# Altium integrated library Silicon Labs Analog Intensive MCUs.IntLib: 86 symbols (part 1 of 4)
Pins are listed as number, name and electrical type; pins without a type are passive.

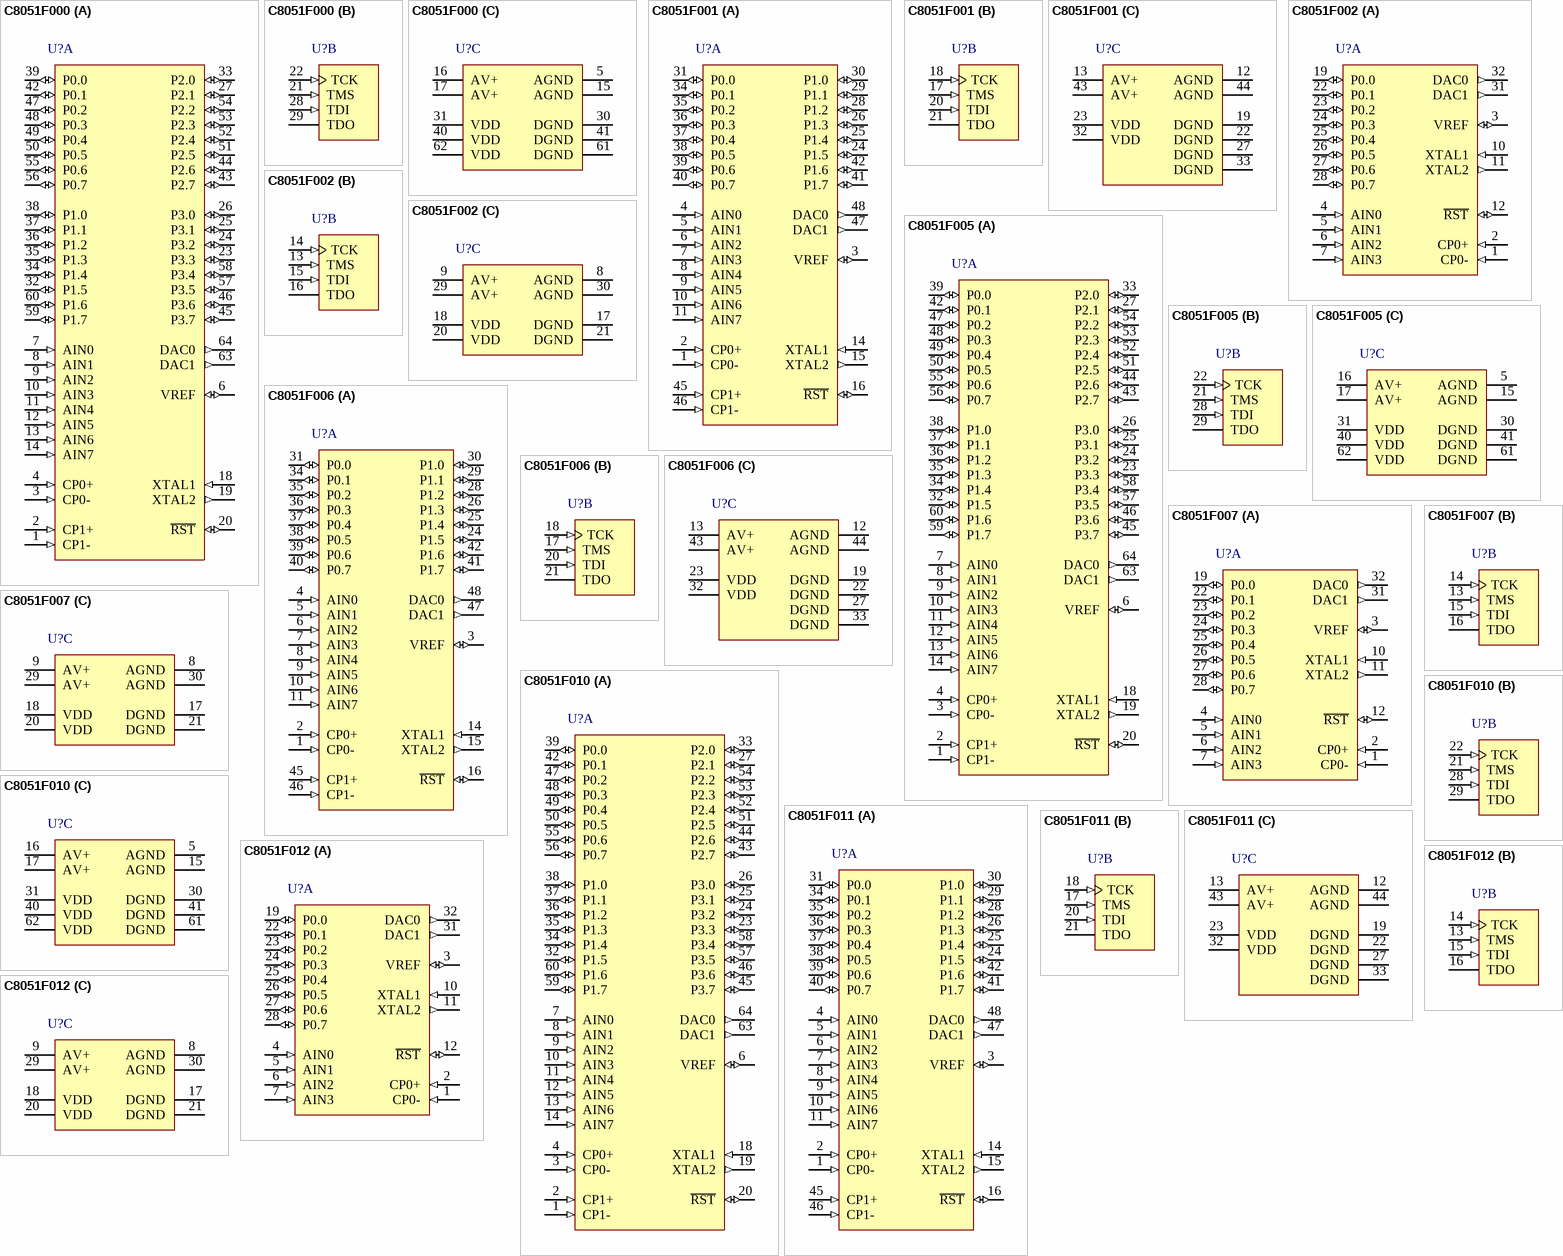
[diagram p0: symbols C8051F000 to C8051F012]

## C8051F000
designator U?
Mixed-Signal 32KB ISP FLASH MCU, 20 MIPS, 256B RAM, 32 I/Os, 12-Bit ADC, 12-Bit DAC, 64-Pin TQFP; Manufacturer: Silicon Labs; PartNumber: C8051F000
footprint TQFP-64_N (Thin QFP, 64-Leads, Body 10x10mm, Pitch 0.5mm, IPC Medium Density)
footprint TQFP-64_L (Thin QFP, 64-Leads, Body 10x10mm, Pitch 0.5mm, IPC High Density)
footprint TQFP-64_M (Thin QFP, 64-Leads, Body 10x10mm, Pitch 0.5mm, IPC Low Density)
part A pins: 1 CP1- (in), 2 CP1+ (in), 3 CP0- (in), 4 CP0+ (in), 6 VREF (io), 7 AIN0 (in), 8 AIN1 (in), 9 AIN2 (in), 10 AIN3 (in), 11 AIN4 (in), 12 AIN5 (in), 13 AIN6 (in), 14 AIN7 (in), 18 XTAL1 (in), 19 XTAL2 (out), 20 ~{RST} (io), 23 P3.3 (io), 24 P3.2 (io), 25 P3.1 (io), 26 P3.0 (io), 27 P2.1 (io), 32 P1.5 (io), 33 P2.0 (io), 34 P1.4 (io), 35 P1.3 (io), 36 P1.2 (io), 37 P1.1 (io), 38 P1.0 (io), 39 P0.0 (io), 42 P0.1 (io), 43 P2.7 (io), 44 P2.6 (io), 45 P3.7 (io), 46 P3.6 (io), 47 P0.2 (io), 48 P0.3 (io), 49 P0.4 (io), 50 P0.5 (io), 51 P2.5 (io), 52 P2.4 (io), 53 P2.3 (io), 54 P2.2 (io), 55 P0.6 (io), 56 P0.7 (io), 57 P3.5 (io), 58 P3.4 (io), 59 P1.7 (io), 60 P1.6 (io), 63 DAC1 (out), 64 DAC0 (out)
part B pins: 21 TMS (in), 22 TCK (in), 28 TDI (in), 29 TDO (hiz)
part C pins: 5 AGND (power), 15 AGND (power), 16 AV+ (power), 17 AV+ (power), 30 DGND (power), 31 VDD (power), 40 VDD (power), 41 DGND (power), 61 DGND (power), 62 VDD (power)

## C8051F001
designator U?
Mixed-Signal 32KB ISP FLASH MCU, 20 MIPS, 256B RAM, 16 I/Os, 12-Bit ADC, 12-Bit DAC, 48-Pin TQFP; Manufacturer: Silicon Labs; PartNumber: C8051F001
footprint TQFP-48_N (Thin QFP, 48-Leads, Body 7x7mm, Pitch 0.5mm, IPC Medium Density)
footprint TQFP-48_L (Thin QFP, 48-Leads, Body 7x7mm, Pitch 0.5mm, IPC High Density)
footprint TQFP-48_M (Thin QFP, 48-Leads, Body 7x7mm, Pitch 0.5mm, IPC Low Density)
part A pins: 1 CP0- (in), 2 CP0+ (in), 3 VREF (io), 4 AIN0 (in), 5 AIN1 (in), 6 AIN2 (in), 7 AIN3 (in), 8 AIN4 (in), 9 AIN5 (in), 10 AIN6 (in), 11 AIN7 (in), 14 XTAL1 (in), 15 XTAL2 (out), 16 ~{RST} (io), 24 P1.5 (io), 25 P1.4 (io), 26 P1.3 (io), 28 P1.2 (io), 29 P1.1 (io), 30 P1.0 (io), 31 P0.0 (io), 34 P0.1 (io), 35 P0.2 (io), 36 P0.3 (io), 37 P0.4 (io), 38 P0.5 (io), 39 P0.6 (io), 40 P0.7 (io), 41 P1.7 (io), 42 P1.6 (io), 45 CP1+ (in), 46 CP1- (in), 47 DAC1 (out), 48 DAC0 (out)
part B pins: 17 TMS (in), 18 TCK (in), 20 TDI (in), 21 TDO (hiz)
part C pins: 12 AGND (power), 13 AV+ (power), 19 DGND (power), 22 DGND (power), 23 VDD (power), 27 DGND (power), 32 VDD (power), 33 DGND (power), 43 AV+ (power), 44 AGND (power)

## C8051F002
designator U?
Mixed-Signal 32KB ISP FLASH MCU, 20 MIPS, 256B RAM, 8 I/Os, 12-Bit ADC, 12-Bit DAC, 32-Pin LQFP; Manufacturer: Silicon Labs; PartNumber: C8051F002
footprint LQFP-32_N (Thin QFP, 32-Leads, Body 7x7mm, Pitch 0.8mm, IPC Medium Density)
footprint LQFP-32_L (Thin QFP, 32-Leads, Body 7x7mm, Pitch 0.8mm, IPC High Density)
footprint LQFP-32_M (Thin QFP, 32-Leads, Body 7x7mm, Pitch 0.8mm, IPC Low Density)
part A pins: 1 CP0- (in), 2 CP0+ (in), 3 VREF (io), 4 AIN0 (in), 5 AIN1 (in), 6 AIN2 (in), 7 AIN3 (in), 10 XTAL1 (in), 11 XTAL2 (out), 12 ~{RST} (io), 19 P0.0 (io), 22 P0.1 (io), 23 P0.2 (io), 24 P0.3 (io), 25 P0.4 (io), 26 P0.5 (io), 27 P0.6 (io), 28 P0.7 (io), 31 DAC1 (out), 32 DAC0 (out)
part B pins: 13 TMS (in), 14 TCK (in), 15 TDI (in), 16 TDO (hiz)
part C pins: 8 AGND (power), 9 AV+ (power), 17 DGND (power), 18 VDD (power), 20 VDD (power), 21 DGND (power), 29 AV+ (power), 30 AGND (power)

## C8051F005
designator U?
Mixed-Signal 32KB ISP FLASH MCU, 25 MIPS, 2304B RAM, 32 I/Os, 12-Bit ADC, 12-Bit DAC, 64-Pin TQFP; Manufacturer: Silicon Labs; PartNumber: C8051F005
footprint TQFP-64_N (Thin QFP, 64-Leads, Body 10x10mm, Pitch 0.5mm, IPC Medium Density)
footprint TQFP-64_L (Thin QFP, 64-Leads, Body 10x10mm, Pitch 0.5mm, IPC High Density)
footprint TQFP-64_M (Thin QFP, 64-Leads, Body 10x10mm, Pitch 0.5mm, IPC Low Density)
part A pins: 1 CP1- (in), 2 CP1+ (in), 3 CP0- (in), 4 CP0+ (in), 6 VREF (io), 7 AIN0 (in), 8 AIN1 (in), 9 AIN2 (in), 10 AIN3 (in), 11 AIN4 (in), 12 AIN5 (in), 13 AIN6 (in), 14 AIN7 (in), 18 XTAL1 (in), 19 XTAL2 (out), 20 ~{RST} (io), 23 P3.3 (io), 24 P3.2 (io), 25 P3.1 (io), 26 P3.0 (io), 27 P2.1 (io), 32 P1.5 (io), 33 P2.0 (io), 34 P1.4 (io), 35 P1.3 (io), 36 P1.2 (io), 37 P1.1 (io), 38 P1.0 (io), 39 P0.0 (io), 42 P0.1 (io), 43 P2.7 (io), 44 P2.6 (io), 45 P3.7 (io), 46 P3.6 (io), 47 P0.2 (io), 48 P0.3 (io), 49 P0.4 (io), 50 P0.5 (io), 51 P2.5 (io), 52 P2.4 (io), 53 P2.3 (io), 54 P2.2 (io), 55 P0.6 (io), 56 P0.7 (io), 57 P3.5 (io), 58 P3.4 (io), 59 P1.7 (io), 60 P1.6 (io), 63 DAC1 (out), 64 DAC0 (out)
part B pins: 21 TMS (in), 22 TCK (in), 28 TDI (in), 29 TDO (hiz)
part C pins: 5 AGND (power), 15 AGND (power), 16 AV+ (power), 17 AV+ (power), 30 DGND (power), 31 VDD (power), 40 VDD (power), 41 DGND (power), 61 DGND (power), 62 VDD (power)

## C8051F006
designator U?
Mixed-Signal 32KB ISP FLASH MCU, 25 MIPS, 2304B RAM, 16 I/Os, 12-Bit ADC, 12-Bit DAC, 48-Pin TQFP; Manufacturer: Silicon Labs; PartNumber: C8051F006
footprint TQFP-48_N (Thin QFP, 48-Leads, Body 7x7mm, Pitch 0.5mm, IPC Medium Density)
footprint TQFP-48_L (Thin QFP, 48-Leads, Body 7x7mm, Pitch 0.5mm, IPC High Density)
footprint TQFP-48_M (Thin QFP, 48-Leads, Body 7x7mm, Pitch 0.5mm, IPC Low Density)
part A pins: 1 CP0- (in), 2 CP0+ (in), 3 VREF (io), 4 AIN0 (in), 5 AIN1 (in), 6 AIN2 (in), 7 AIN3 (in), 8 AIN4 (in), 9 AIN5 (in), 10 AIN6 (in), 11 AIN7 (in), 14 XTAL1 (in), 15 XTAL2 (out), 16 ~{RST} (io), 24 P1.5 (io), 25 P1.4 (io), 26 P1.3 (io), 28 P1.2 (io), 29 P1.1 (io), 30 P1.0 (io), 31 P0.0 (io), 34 P0.1 (io), 35 P0.2 (io), 36 P0.3 (io), 37 P0.4 (io), 38 P0.5 (io), 39 P0.6 (io), 40 P0.7 (io), 41 P1.7 (io), 42 P1.6 (io), 45 CP1+ (in), 46 CP1- (in), 47 DAC1 (out), 48 DAC0 (out)
part B pins: 17 TMS (in), 18 TCK (in), 20 TDI (in), 21 TDO (hiz)
part C pins: 12 AGND (power), 13 AV+ (power), 19 DGND (power), 22 DGND (power), 23 VDD (power), 27 DGND (power), 32 VDD (power), 33 DGND (power), 43 AV+ (power), 44 AGND (power)

## C8051F007
designator U?
Mixed-Signal 32KB ISP FLASH MCU, 25 MIPS, 2304B RAM, 8 I/Os, 12-Bit ADC, 12-Bit DAC, 32-Pin LQFP; Manufacturer: Silicon Labs; PartNumber: C8051F007
footprint LQFP-32_N (Thin QFP, 32-Leads, Body 7x7mm, Pitch 0.8mm, IPC Medium Density)
footprint LQFP-32_L (Thin QFP, 32-Leads, Body 7x7mm, Pitch 0.8mm, IPC High Density)
footprint LQFP-32_M (Thin QFP, 32-Leads, Body 7x7mm, Pitch 0.8mm, IPC Low Density)
part A pins: 1 CP0- (in), 2 CP0+ (in), 3 VREF (io), 4 AIN0 (in), 5 AIN1 (in), 6 AIN2 (in), 7 AIN3 (in), 10 XTAL1 (in), 11 XTAL2 (out), 12 ~{RST} (io), 19 P0.0 (io), 22 P0.1 (io), 23 P0.2 (io), 24 P0.3 (io), 25 P0.4 (io), 26 P0.5 (io), 27 P0.6 (io), 28 P0.7 (io), 31 DAC1 (out), 32 DAC0 (out)
part B pins: 13 TMS (in), 14 TCK (in), 15 TDI (in), 16 TDO (hiz)
part C pins: 8 AGND (power), 9 AV+ (power), 17 DGND (power), 18 VDD (power), 20 VDD (power), 21 DGND (power), 29 AV+ (power), 30 AGND (power)

## C8051F010
designator U?
Mixed-Signal 32KB ISP FLASH MCU, 20 MIPS, 256B RAM, 32 I/Os, 10-Bit ADC, 12-Bit DAC, 64-Pin TQFP; Manufacturer: Silicon Labs; PartNumber: C8051F010
footprint TQFP-64_N (Thin QFP, 64-Leads, Body 10x10mm, Pitch 0.5mm, IPC Medium Density)
footprint TQFP-64_L (Thin QFP, 64-Leads, Body 10x10mm, Pitch 0.5mm, IPC High Density)
footprint TQFP-64_M (Thin QFP, 64-Leads, Body 10x10mm, Pitch 0.5mm, IPC Low Density)
part A pins: 1 CP1- (in), 2 CP1+ (in), 3 CP0- (in), 4 CP0+ (in), 6 VREF (io), 7 AIN0 (in), 8 AIN1 (in), 9 AIN2 (in), 10 AIN3 (in), 11 AIN4 (in), 12 AIN5 (in), 13 AIN6 (in), 14 AIN7 (in), 18 XTAL1 (in), 19 XTAL2 (out), 20 ~{RST} (io), 23 P3.3 (io), 24 P3.2 (io), 25 P3.1 (io), 26 P3.0 (io), 27 P2.1 (io), 32 P1.5 (io), 33 P2.0 (io), 34 P1.4 (io), 35 P1.3 (io), 36 P1.2 (io), 37 P1.1 (io), 38 P1.0 (io), 39 P0.0 (io), 42 P0.1 (io), 43 P2.7 (io), 44 P2.6 (io), 45 P3.7 (io), 46 P3.6 (io), 47 P0.2 (io), 48 P0.3 (io), 49 P0.4 (io), 50 P0.5 (io), 51 P2.5 (io), 52 P2.4 (io), 53 P2.3 (io), 54 P2.2 (io), 55 P0.6 (io), 56 P0.7 (io), 57 P3.5 (io), 58 P3.4 (io), 59 P1.7 (io), 60 P1.6 (io), 63 DAC1 (out), 64 DAC0 (out)
part B pins: 21 TMS (in), 22 TCK (in), 28 TDI (in), 29 TDO (hiz)
part C pins: 5 AGND (power), 15 AGND (power), 16 AV+ (power), 17 AV+ (power), 30 DGND (power), 31 VDD (power), 40 VDD (power), 41 DGND (power), 61 DGND (power), 62 VDD (power)

## C8051F011
designator U?
Mixed-Signal 32KB ISP FLASH MCU, 20 MIPS, 256B RAM, 16 I/Os, 10-Bit ADC, 12-Bit DAC, 48-Pin TQFP; Manufacturer: Silicon Labs; PartNumber: C8051F011
footprint TQFP-48_N (Thin QFP, 48-Leads, Body 7x7mm, Pitch 0.5mm, IPC Medium Density)
footprint TQFP-48_L (Thin QFP, 48-Leads, Body 7x7mm, Pitch 0.5mm, IPC High Density)
footprint TQFP-48_M (Thin QFP, 48-Leads, Body 7x7mm, Pitch 0.5mm, IPC Low Density)
part A pins: 1 CP0- (in), 2 CP0+ (in), 3 VREF (io), 4 AIN0 (in), 5 AIN1 (in), 6 AIN2 (in), 7 AIN3 (in), 8 AIN4 (in), 9 AIN5 (in), 10 AIN6 (in), 11 AIN7 (in), 14 XTAL1 (in), 15 XTAL2 (out), 16 ~{RST} (io), 24 P1.5 (io), 25 P1.4 (io), 26 P1.3 (io), 28 P1.2 (io), 29 P1.1 (io), 30 P1.0 (io), 31 P0.0 (io), 34 P0.1 (io), 35 P0.2 (io), 36 P0.3 (io), 37 P0.4 (io), 38 P0.5 (io), 39 P0.6 (io), 40 P0.7 (io), 41 P1.7 (io), 42 P1.6 (io), 45 CP1+ (in), 46 CP1- (in), 47 DAC1 (out), 48 DAC0 (out)
part B pins: 17 TMS (in), 18 TCK (in), 20 TDI (in), 21 TDO (hiz)
part C pins: 12 AGND (power), 13 AV+ (power), 19 DGND (power), 22 DGND (power), 23 VDD (power), 27 DGND (power), 32 VDD (power), 33 DGND (power), 43 AV+ (power), 44 AGND (power)

## C8051F012
designator U?
Mixed-Signal 32KB ISP FLASH MCU, 20 MIPS, 256B RAM, 8 I/Os, 10-Bit ADC, 12-Bit DAC, 32-Pin LQFP; Manufacturer: Silicon Labs; PartNumber: C8051F012
footprint LQFP-32_N (Thin QFP, 32-Leads, Body 7x7mm, Pitch 0.8mm, IPC Medium Density)
footprint LQFP-32_L (Thin QFP, 32-Leads, Body 7x7mm, Pitch 0.8mm, IPC High Density)
footprint LQFP-32_M (Thin QFP, 32-Leads, Body 7x7mm, Pitch 0.8mm, IPC Low Density)
part A pins: 1 CP0- (in), 2 CP0+ (in), 3 VREF (io), 4 AIN0 (in), 5 AIN1 (in), 6 AIN2 (in), 7 AIN3 (in), 10 XTAL1 (in), 11 XTAL2 (out), 12 ~{RST} (io), 19 P0.0 (io), 22 P0.1 (io), 23 P0.2 (io), 24 P0.3 (io), 25 P0.4 (io), 26 P0.5 (io), 27 P0.6 (io), 28 P0.7 (io), 31 DAC1 (out), 32 DAC0 (out)
part B pins: 13 TMS (in), 14 TCK (in), 15 TDI (in), 16 TDO (hiz)
part C pins: 8 AGND (power), 9 AV+ (power), 17 DGND (power), 18 VDD (power), 20 VDD (power), 21 DGND (power), 29 AV+ (power), 30 AGND (power)

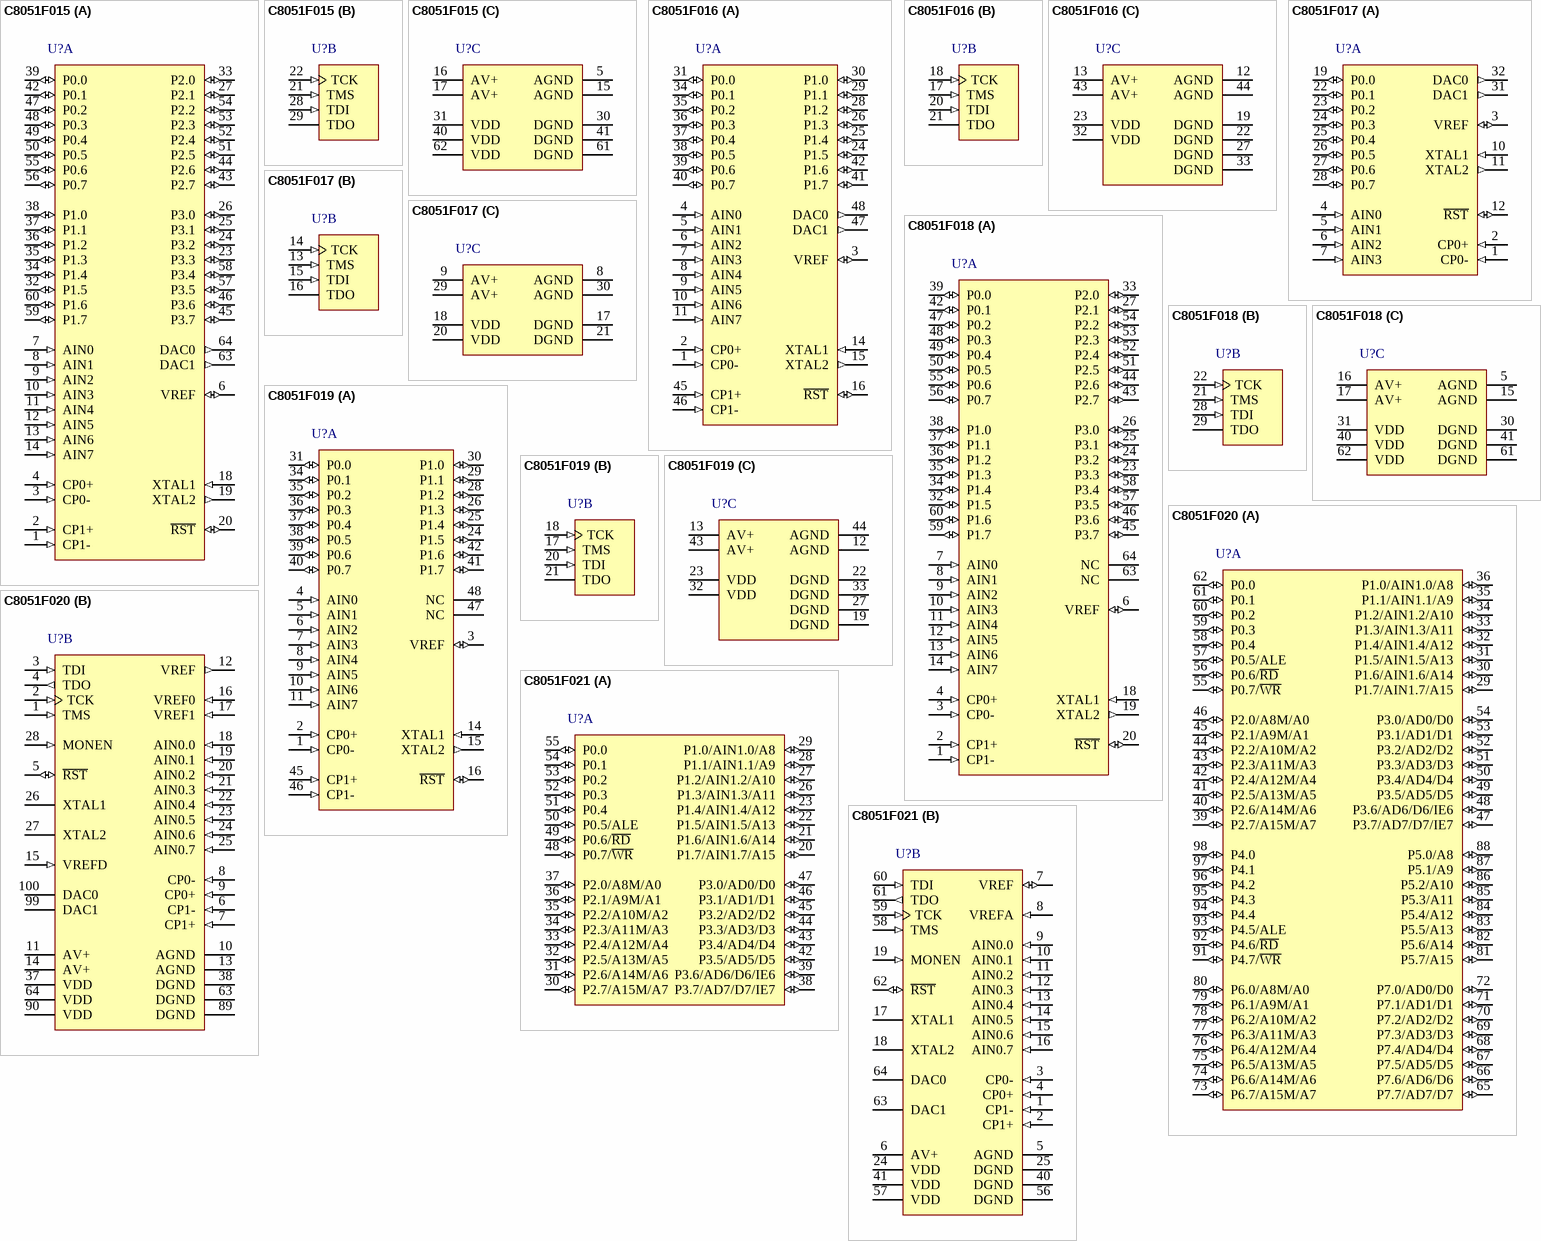
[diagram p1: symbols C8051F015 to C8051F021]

## C8051F015
designator U?
Mixed-Signal 32KB ISP FLASH MCU, 25 MIPS, 2304B RAM, 32 I/Os, 10-Bit ADC, 12-Bit DAC, 64-Pin TQFP; Manufacturer: Silicon Labs; PartNumber: C8051F015
footprint TQFP-64_N (Thin QFP, 64-Leads, Body 10x10mm, Pitch 0.5mm, IPC Medium Density)
footprint TQFP-64_L (Thin QFP, 64-Leads, Body 10x10mm, Pitch 0.5mm, IPC High Density)
footprint TQFP-64_M (Thin QFP, 64-Leads, Body 10x10mm, Pitch 0.5mm, IPC Low Density)
part A pins: 1 CP1- (in), 2 CP1+ (in), 3 CP0- (in), 4 CP0+ (in), 6 VREF (io), 7 AIN0 (in), 8 AIN1 (in), 9 AIN2 (in), 10 AIN3 (in), 11 AIN4 (in), 12 AIN5 (in), 13 AIN6 (in), 14 AIN7 (in), 18 XTAL1 (in), 19 XTAL2 (out), 20 ~{RST} (io), 23 P3.3 (io), 24 P3.2 (io), 25 P3.1 (io), 26 P3.0 (io), 27 P2.1 (io), 32 P1.5 (io), 33 P2.0 (io), 34 P1.4 (io), 35 P1.3 (io), 36 P1.2 (io), 37 P1.1 (io), 38 P1.0 (io), 39 P0.0 (io), 42 P0.1 (io), 43 P2.7 (io), 44 P2.6 (io), 45 P3.7 (io), 46 P3.6 (io), 47 P0.2 (io), 48 P0.3 (io), 49 P0.4 (io), 50 P0.5 (io), 51 P2.5 (io), 52 P2.4 (io), 53 P2.3 (io), 54 P2.2 (io), 55 P0.6 (io), 56 P0.7 (io), 57 P3.5 (io), 58 P3.4 (io), 59 P1.7 (io), 60 P1.6 (io), 63 DAC1 (out), 64 DAC0 (out)
part B pins: 21 TMS (in), 22 TCK (in), 28 TDI (in), 29 TDO (hiz)
part C pins: 5 AGND (power), 15 AGND (power), 16 AV+ (power), 17 AV+ (power), 30 DGND (power), 31 VDD (power), 40 VDD (power), 41 DGND (power), 61 DGND (power), 62 VDD (power)

## C8051F016
designator U?
Mixed-Signal 32KB ISP FLASH MCU, 25 MIPS, 2304B RAM, 16 I/Os, 10-Bit ADC, 12-Bit DAC, 48-Pin TQFP; Manufacturer: Silicon Labs; PartNumber: C8051F016
footprint TQFP-48_N (Thin QFP, 48-Leads, Body 7x7mm, Pitch 0.5mm, IPC Medium Density)
footprint TQFP-48_L (Thin QFP, 48-Leads, Body 7x7mm, Pitch 0.5mm, IPC High Density)
footprint TQFP-48_M (Thin QFP, 48-Leads, Body 7x7mm, Pitch 0.5mm, IPC Low Density)
part A pins: 1 CP0- (in), 2 CP0+ (in), 3 VREF (io), 4 AIN0 (in), 5 AIN1 (in), 6 AIN2 (in), 7 AIN3 (in), 8 AIN4 (in), 9 AIN5 (in), 10 AIN6 (in), 11 AIN7 (in), 14 XTAL1 (in), 15 XTAL2 (out), 16 ~{RST} (io), 24 P1.5 (io), 25 P1.4 (io), 26 P1.3 (io), 28 P1.2 (io), 29 P1.1 (io), 30 P1.0 (io), 31 P0.0 (io), 34 P0.1 (io), 35 P0.2 (io), 36 P0.3 (io), 37 P0.4 (io), 38 P0.5 (io), 39 P0.6 (io), 40 P0.7 (io), 41 P1.7 (io), 42 P1.6 (io), 45 CP1+ (in), 46 CP1- (in), 47 DAC1 (out), 48 DAC0 (out)
part B pins: 17 TMS (in), 18 TCK (in), 20 TDI (in), 21 TDO (hiz)
part C pins: 12 AGND (power), 13 AV+ (power), 19 DGND (power), 22 DGND (power), 23 VDD (power), 27 DGND (power), 32 VDD (power), 33 DGND (power), 43 AV+ (power), 44 AGND (power)

## C8051F017
designator U?
Mixed-Signal 32KB ISP FLASH MCU, 25 MIPS, 2304B RAM, 8 I/Os, 10-Bit ADC, 12-Bit DAC, 32-Pin LQFP; Manufacturer: Silicon Labs; PartNumber: C8051F017
footprint LQFP-32_N (Thin QFP, 32-Leads, Body 7x7mm, Pitch 0.8mm, IPC Medium Density)
footprint LQFP-32_L (Thin QFP, 32-Leads, Body 7x7mm, Pitch 0.8mm, IPC High Density)
footprint LQFP-32_M (Thin QFP, 32-Leads, Body 7x7mm, Pitch 0.8mm, IPC Low Density)
part A pins: 1 CP0- (in), 2 CP0+ (in), 3 VREF (io), 4 AIN0 (in), 5 AIN1 (in), 6 AIN2 (in), 7 AIN3 (in), 10 XTAL1 (in), 11 XTAL2 (out), 12 ~{RST} (io), 19 P0.0 (io), 22 P0.1 (io), 23 P0.2 (io), 24 P0.3 (io), 25 P0.4 (io), 26 P0.5 (io), 27 P0.6 (io), 28 P0.7 (io), 31 DAC1 (out), 32 DAC0 (out)
part B pins: 13 TMS (in), 14 TCK (in), 15 TDI (in), 16 TDO (hiz)
part C pins: 8 AGND (power), 9 AV+ (power), 17 DGND (power), 18 VDD (power), 20 VDD (power), 21 DGND (power), 29 AV+ (power), 30 AGND (power)

## C8051F018
designator U?
Mixed-Signal 16KB ISP FLASH MCU, 25 MIPS, 1280B RAM, 32 I/Os, 10-Bit ADC, 64-Pin TQFP; Manufacturer: Silicon Labs; PartNumber: C8051F018
footprint TQFP-64_N (Thin QFP, 64-Leads, Body 10x10mm, Pitch 0.5mm, IPC Medium Density)
footprint TQFP-64_L (Thin QFP, 64-Leads, Body 10x10mm, Pitch 0.5mm, IPC High Density)
footprint TQFP-64_M (Thin QFP, 64-Leads, Body 10x10mm, Pitch 0.5mm, IPC Low Density)
part A pins: 1 CP1- (in), 2 CP1+ (in), 3 CP0- (in), 4 CP0+ (in), 6 VREF (io), 7 AIN0 (in), 8 AIN1 (in), 9 AIN2 (in), 10 AIN3 (in), 11 AIN4 (in), 12 AIN5 (in), 13 AIN6 (in), 14 AIN7 (in), 18 XTAL1 (in), 19 XTAL2 (out), 20 ~{RST} (io), 23 P3.3 (io), 24 P3.2 (io), 25 P3.1 (io), 26 P3.0 (io), 27 P2.1 (io), 32 P1.5 (io), 33 P2.0 (io), 34 P1.4 (io), 35 P1.3 (io), 36 P1.2 (io), 37 P1.1 (io), 38 P1.0 (io), 39 P0.0 (io), 42 P0.1 (io), 43 P2.7 (io), 44 P2.6 (io), 45 P3.7 (io), 46 P3.6 (io), 47 P0.2 (io), 48 P0.3 (io), 49 P0.4 (io), 50 P0.5 (io), 51 P2.5 (io), 52 P2.4 (io), 53 P2.3 (io), 54 P2.2 (io), 55 P0.6 (io), 56 P0.7 (io), 57 P3.5 (io), 58 P3.4 (io), 59 P1.7 (io), 60 P1.6 (io), 63 NC, 64 NC
part B pins: 21 TMS (in), 22 TCK (in), 28 TDI (in), 29 TDO (hiz)
part C pins: 5 AGND (power), 15 AGND (power), 16 AV+ (power), 17 AV+ (power), 30 DGND (power), 31 VDD (power), 40 VDD (power), 41 DGND (power), 61 DGND (power), 62 VDD (power)

## C8051F019
designator U?
Mixed-Signal 16KB ISP FLASH MCU, 25 MIPS, 1280B RAM, 16 I/Os, 10-Bit ADC, 48-Pin TQFP; Manufacturer: Silicon Labs; PartNumber: C8051F019
footprint TQFP-48_N (Thin QFP, 48-Leads, Body 7x7mm, Pitch 0.5mm, IPC Medium Density)
footprint TQFP-48_L (Thin QFP, 48-Leads, Body 7x7mm, Pitch 0.5mm, IPC High Density)
footprint TQFP-48_M (Thin QFP, 48-Leads, Body 7x7mm, Pitch 0.5mm, IPC Low Density)
part A pins: 1 CP0- (in), 2 CP0+ (in), 3 VREF (io), 4 AIN0 (in), 5 AIN1 (in), 6 AIN2 (in), 7 AIN3 (in), 8 AIN4 (in), 9 AIN5 (in), 10 AIN6 (in), 11 AIN7 (in), 14 XTAL1 (in), 15 XTAL2 (out), 16 ~{RST} (io), 24 P1.5 (io), 25 P1.4 (io), 26 P1.3 (io), 28 P1.2 (io), 29 P1.1 (io), 30 P1.0 (io), 31 P0.0 (io), 34 P0.1 (io), 35 P0.2 (io), 36 P0.3 (io), 37 P0.4 (io), 38 P0.5 (io), 39 P0.6 (io), 40 P0.7 (io), 41 P1.7 (io), 42 P1.6 (io), 45 CP1+ (in), 46 CP1- (in), 47 NC, 48 NC
part B pins: 17 TMS (in), 18 TCK (in), 20 TDI (in), 21 TDO (hiz)
part C pins: 12 AGND (power), 13 AV+ (power), 19 DGND (power), 22 DGND (power), 23 VDD (power), 27 DGND (power), 32 VDD (power), 33 DGND (power), 43 AV+ (power), 44 AGND (power)

## C8051F020
designator U?
ISP Flash MCU Family, 25 MHz, 4.25 kB RAM, 64 kB Flash, -40 to 85 degC, 100-pin QFP; Manufacturer: Silicon Labs; PartNumber: C8051F020; ADC 1: 12-bit, 8-ch., 100 ksps; ADC 2: 8-bit, 8-ch., 500 ksps; AEC-Q100: FALSE; Comparators: 2; DAC: 12-bit, 2-ch.; Debug Interface: JTAG; Dig I/O Pins: 64; Flash: 64 kB; Internal Osc. Accuracy: +/-20%; MCU Core: 8051; MHz: 25; PCA Channels: 5; RAM: 4.25 kB; Temp Sensor: TRUE; Sub-Family: Analog Intensive MCUs
footprint SLAB-TQFP-100_N (QFP, 100-Leads, Body 14x14mm, Pitch 0.5mm, IPC Medium Density)
footprint SLAB-TQFP-100_L (QFP, 100-Leads, Body 14x14mm, Pitch 0.5mm, IPC High Density)
footprint SLAB-TQFP-100_M (QFP, 100-Leads, Body 14x14mm, Pitch 0.5mm, IPC Low Density)
part A pins: 29 P1.7/AIN1.7/A15 (io), 30 P1.6/AIN1.6/A14 (io), 31 P1.5/AIN1.5/A13 (io), 32 P1.4/AIN1.4/A12 (io), 33 P1.3/AIN1.3/A11 (io), 34 P1.2/AIN1.2/A10 (io), 35 P1.1/AIN1.1/A9 (io), 36 P1.0/AIN1.0/A8 (io), 39 P2.7/A15M/A7 (io), 40 P2.6/A14M/A6 (io), 41 P2.5/A13M/A5 (io), 42 P2.4/A12M/A4 (io), 43 P2.3/A11M/A3 (io), 44 P2.2/A10M/A2 (io), 45 P2.1/A9M/A1 (io), 46 P2.0/A8M/A0 (io), 47 P3.7/AD7/D7/IE7 (io), 48 P3.6/AD6/D6/IE6 (io), 49 P3.5/AD5/D5 (io), 50 P3.4/AD4/D4 (io), 51 P3.3/AD3/D3 (io), 52 P3.2/AD2/D2 (io), 53 P3.1/AD1/D1 (io), 54 P3.0/AD0/D0 (io), 55 P0.7/~{WR} (io), 56 P0.6/~{RD} (io), 57 P0.5/ALE (io), 58 P0.4 (io) "Port 0.4. See Port Input/Output section for complete description.", 59 P0.3 (io) "Port 0.3. See Port Input/Output section for complete description.", 60 P0.2 (io) "Port 0.2. See Port Input/Output section for complete description.", 61 P0.1 (io) "Port 0.1. See Port Input/Output section for complete description.", 62 P0.0 (io) "Port 0.0. See Port Input/Output section for complete description.", 65 P7.7/AD7/D7 (io), 66 P7.6/AD6/D6 (io), 67 P7.5/AD5/D5 (io), 68 P7.4/AD4/D4 (io), 69 P7.3/AD3/D3 (io), 70 P7.2/AD2/D2 (io), 71 P7.1/AD1/D1 (io), 72 P7.0/AD0/D0 (io), 73 P6.7/A15M/A7 (io), 74 P6.6/A14M/A6 (io), 75 P6.5/A13M/A5 (io), 76 P6.4/A12M/A4 (io), 77 P6.3/A11M/A3 (io), 78 P6.2/A10M/A2 (io), 79 P6.1/A9M/A1 (io), 80 P6.0/A8M/A0 (io), 81 P5.7/A15 (io), 82 P5.6/A14 (io), 83 P5.5/A13 (io), 84 P5.4/A12 (io), 85 P5.3/A11 (io), 86 P5.2/A10 (io), 87 P5.1/A9 (io), 88 P5.0/A8 (io), 91 P4.7/~{WR} (io), 92 P4.6/~{RD} (io), 93 P4.5/ALE (io), 94 P4.4 (io) "Port 4.4. See Port Input/Output section for complete description.", 95 P4.3 (io) "Port 4.3. See Port Input/Output section for complete description.", 96 P4.2 (io) "Port 4.2. See Port Input/Output section for complete description.", 97 P4.1 (io) "Port 4.1. See Port Input/Output section for complete description.", 98 P4.0 (io) "Port 4.0. See Port Input/Output section for complete description."
part B pins: 1 TMS (in) "JTAG Test Mode Select with internal pull-up.", 2 TCK (in) "JTAG Test Clock with internal pull-up.", 3 TDI (in) "JTAG Test Data Input with internal pull-up. TDI is latched on the rising edge of TCK.", 4 TDO (out) "JTAG Test Data Output with internal pull-up. Data is shifted out on TDO on the falling edge of TCK. TDO output is a tri-state driver.", 5 ~{RST} (io) "Device Reset. Open-drain output of internal VDD monitor. Is driven low when VDD is <2.7 V and MONEN is high. An external source can initiate a system reset by driving this pin low.", 6 CP1- (in) "Comparator 1 Inverting Input.", 7 CP1+ (in) "Comparator 1 Non-Inverting Input.", 8 CP0- (in) "Comparator 0 Inverting Input.", 9 CP0+ (in) "Comparator 0 Non-Inverting Input.", 10 AGND (power) "Analog Ground. Must be tied to Ground.", 11 AV+ (power) "Analog Supply Voltage. Must be tied to +2.7 to +3.6 V.", 12 VREF (out) "Bandgap Voltage Reference Output (all devices). DAC Voltage Reference Input (F021/3 only).", 13 AGND (power) "Analog Ground. Must be tied to Ground.", 14 AV+ (power) "Analog Supply Voltage. Must be tied to +2.7 to +3.6 V.", 15 VREFD (in) "DAC Voltage Reference Input.", 16 VREF0 (in) "ADC0 Voltage Reference Input.", 17 VREF1 (in) "ADC1 Voltage Reference Input.", 18 AIN0.0 (in) "ADC0 Input Channel 0 (See ADC0 Specification for complete description).", 19 AIN0.1 (in) "ADC0 Input Channel 1 (See ADC0 Specification for complete description).", 20 AIN0.2 (in) "ADC0 Input Channel 2 (See ADC0 Specification for complete description).", 21 AIN0.3 (in) "ADC0 Input Channel 3 (See ADC0 Specification for complete description).", 22 AIN0.4 (in) "ADC0 Input Channel 4 (See ADC0 Specification for complete description).", 23 AIN0.5 (in) "ADC0 Input Channel 5 (See ADC0 Specification for complete description).", 24 AIN0.6 (in) "ADC0 Input Channel 6 (See ADC0 Specification for complete description).", 25 AIN0.7 (in) "ADC0 Input Channel 7 (See ADC0 Specification for complete description).", 26 XTAL1 "Crystal Input. This pin is the return for the internal oscillator circuit for a crystal or ceramic resonator. For a precision internal clock, connect a crystal or ceramic resonator from XTAL1 to XTAL2. If overdriven by an (See Datasheet)", 27 XTAL2 "Crystal Output. This pin is the excitation driver for a crystal or ceramic resonator.", 28 MONEN (in) "VDD Monitor Enable. When tied high, this pin enables the internal VDD monitor, which forces a system reset when VDD is < 2.7 V. When tied low, the internal VDD monitor is disabled.", 37 VDD (power) "Digital Supply Voltage. Must be tied to +2.7 to +3.6 V.", 38 DGND (power) "Digital Ground. Must be tied to Ground.", 63 DGND (power) "Digital Ground. Must be tied to Ground.", 64 VDD (power) "Digital Supply Voltage. Must be tied to +2.7 to +3.6 V.", 89 DGND (power) "Digital Ground. Must be tied to Ground.", 90 VDD (power) "Digital Supply Voltage. Must be tied to +2.7 to +3.6 V.", 99 DAC1 (hiz) "Digital to Analog Converter 1 Voltage Output. (See DAC Specifica- tion for complete description).", 100 DAC0 (hiz) "Digital to Analog Converter 0 Voltage Output. (See DAC Specifica- tion for complete description)."

## C8051F021
designator U?
ISP Flash MCU Family, 25 MHz, 4.25 kB RAM, 64 kB Flash, -40 to 85 degC, 64-pin QFP; Manufacturer: Silicon Labs; PartNumber: C8051F021; ADC 1: 12-bit, 8-ch., 100 ksps; ADC 2: 8-bit, 8-ch., 500 ksps; AEC-Q100: FALSE; Comparators: 2; DAC: 12-bit, 2-ch.; Debug Interface: JTAG; Dig I/O Pins: 32; Flash: 64 kB; Internal Osc. Accuracy: +/-20%; MCU Core: 8051; MHz: 25; PCA Channels: 5; RAM: 4.25 kB; Temp Sensor: TRUE; Sub-Family: Analog Intensive MCUs
footprint SLAB-TQFP-64_N (QFP, 64-Leads, Body 10x10mm, Pitch 0.5mm, IPC Medium Density)
footprint SLAB-TQFP-64_L (QFP, 64-Leads, Body 10x10mm, Pitch 0.5mm, IPC High Density)
footprint SLAB-TQFP-64_M (QFP, 64-Leads, Body 10x10mm, Pitch 0.5mm, IPC Low Density)
part A pins: 20 P1.7/AIN1.7/A15 (io), 21 P1.6/AIN1.6/A14 (io), 22 P1.5/AIN1.5/A13 (io), 23 P1.4/AIN1.4/A12 (io), 26 P1.3/AIN1.3/A11 (io), 27 P1.2/AIN1.2/A10 (io), 28 P1.1/AIN1.1/A9 (io), 29 P1.0/AIN1.0/A8 (io), 30 P2.7/A15M/A7 (io), 31 P2.6/A14M/A6 (io), 32 P2.5/A13M/A5 (io), 33 P2.4/A12M/A4 (io), 34 P2.3/A11M/A3 (io), 35 P2.2/A10M/A2 (io), 36 P2.1/A9M/A1 (io), 37 P2.0/A8M/A0 (io), 38 P3.7/AD7/D7/IE7 (io), 39 P3.6/AD6/D6/IE6 (io), 42 P3.5/AD5/D5 (io), 43 P3.4/AD4/D4 (io), 44 P3.3/AD3/D3 (io), 45 P3.2/AD2/D2 (io), 46 P3.1/AD1/D1 (io), 47 P3.0/AD0/D0 (io), 48 P0.7/~{WR} (io), 49 P0.6/~{RD} (io), 50 P0.5/ALE (io), 51 P0.4 (io) "Port 0.4. See Port Input/Output section for complete description.", 52 P0.3 (io) "Port 0.3. See Port Input/Output section for complete description.", 53 P0.2 (io) "Port 0.2. See Port Input/Output section for complete description.", 54 P0.1 (io) "Port 0.1. See Port Input/Output section for complete description.", 55 P0.0 (io) "Port 0.0. See Port Input/Output section for complete description."
part B pins: 1 CP1- (in) "Comparator 1 Inverting Input.", 2 CP1+ (in) "Comparator 1 Non-Inverting Input.", 3 CP0- (in) "Comparator 0 Inverting Input.", 4 CP0+ (in) "Comparator 0 Non-Inverting Input.", 5 AGND (power) "Analog Ground. Must be tied to Ground.", 6 AV+ (power) "Analog Supply Voltage. Must be tied to +2.7 to +3.6 V.", 7 VREF (io) "Bandgap Voltage Reference Output (all devices). DAC Voltage Reference Input (F021/3 only).", 8 VREFA (in) "ADC0 and ADC1 Voltage Reference Input.", 9 AIN0.0 (in) "ADC0 Input Channel 0 (See ADC0 Specification for complete description).", 10 AIN0.1 (in) "ADC0 Input Channel 1 (See ADC0 Specification for complete description).", 11 AIN0.2 (in) "ADC0 Input Channel 2 (See ADC0 Specification for complete description).", 12 AIN0.3 (in) "ADC0 Input Channel 3 (See ADC0 Specification for complete description).", 13 AIN0.4 (in) "ADC0 Input Channel 4 (See ADC0 Specification for complete description).", 14 AIN0.5 (in) "ADC0 Input Channel 5 (See ADC0 Specification for complete description).", 15 AIN0.6 (in) "ADC0 Input Channel 6 (See ADC0 Specification for complete description).", 16 AIN0.7 (in) "ADC0 Input Channel 7 (See ADC0 Specification for complete description).", 17 XTAL1 "Crystal Input. This pin is the return for the internal oscillator circuit for a crystal or ceramic resonator. For a precision internal clock, connect a crystal or ceramic resonator from XTAL1 to XTAL2. If overdriven by an (See Datasheet)", 18 XTAL2 "Crystal Output. This pin is the excitation driver for a crystal or ceramic resonator.", 19 MONEN (in) "VDD Monitor Enable. When tied high, this pin enables the internal VDD monitor, which forces a system reset when VDD is < 2.7 V. When tied low, the internal VDD monitor is disabled.", 24 VDD (power) "Digital Supply Voltage. Must be tied to +2.7 to +3.6 V.", 25 DGND (power) "Digital Ground. Must be tied to Ground.", 40 DGND (power) "Digital Ground. Must be tied to Ground.", 41 VDD (power) "Digital Supply Voltage. Must be tied to +2.7 to +3.6 V.", 56 DGND (power) "Digital Ground. Must be tied to Ground.", 57 VDD (power) "Digital Supply Voltage. Must be tied to +2.7 to +3.6 V.", 58 TMS (in) "JTAG Test Mode Select with internal pull-up.", 59 TCK (in) "JTAG Test Clock with internal pull-up.", 60 TDI (in) "JTAG Test Data Input with internal pull-up. TDI is latched on the rising edge of TCK.", 61 TDO (out) "JTAG Test Data Output with internal pull-up. Data is shifted out on TDO on the falling edge of TCK. TDO output is a tri-state driver.", 62 ~{RST} (io) "Device Reset. Open-drain output of internal VDD monitor. Is driven low when VDD is <2.7 V and MONEN is high. An external source can initiate a system reset by driving this pin low.", 63 DAC1 (hiz) "Digital to Analog Converter 1 Voltage Output. (See DAC Specifica- tion for complete description).", 64 DAC0 (hiz) "Digital to Analog Converter 0 Voltage Output. (See DAC Specifica- tion for complete description)."

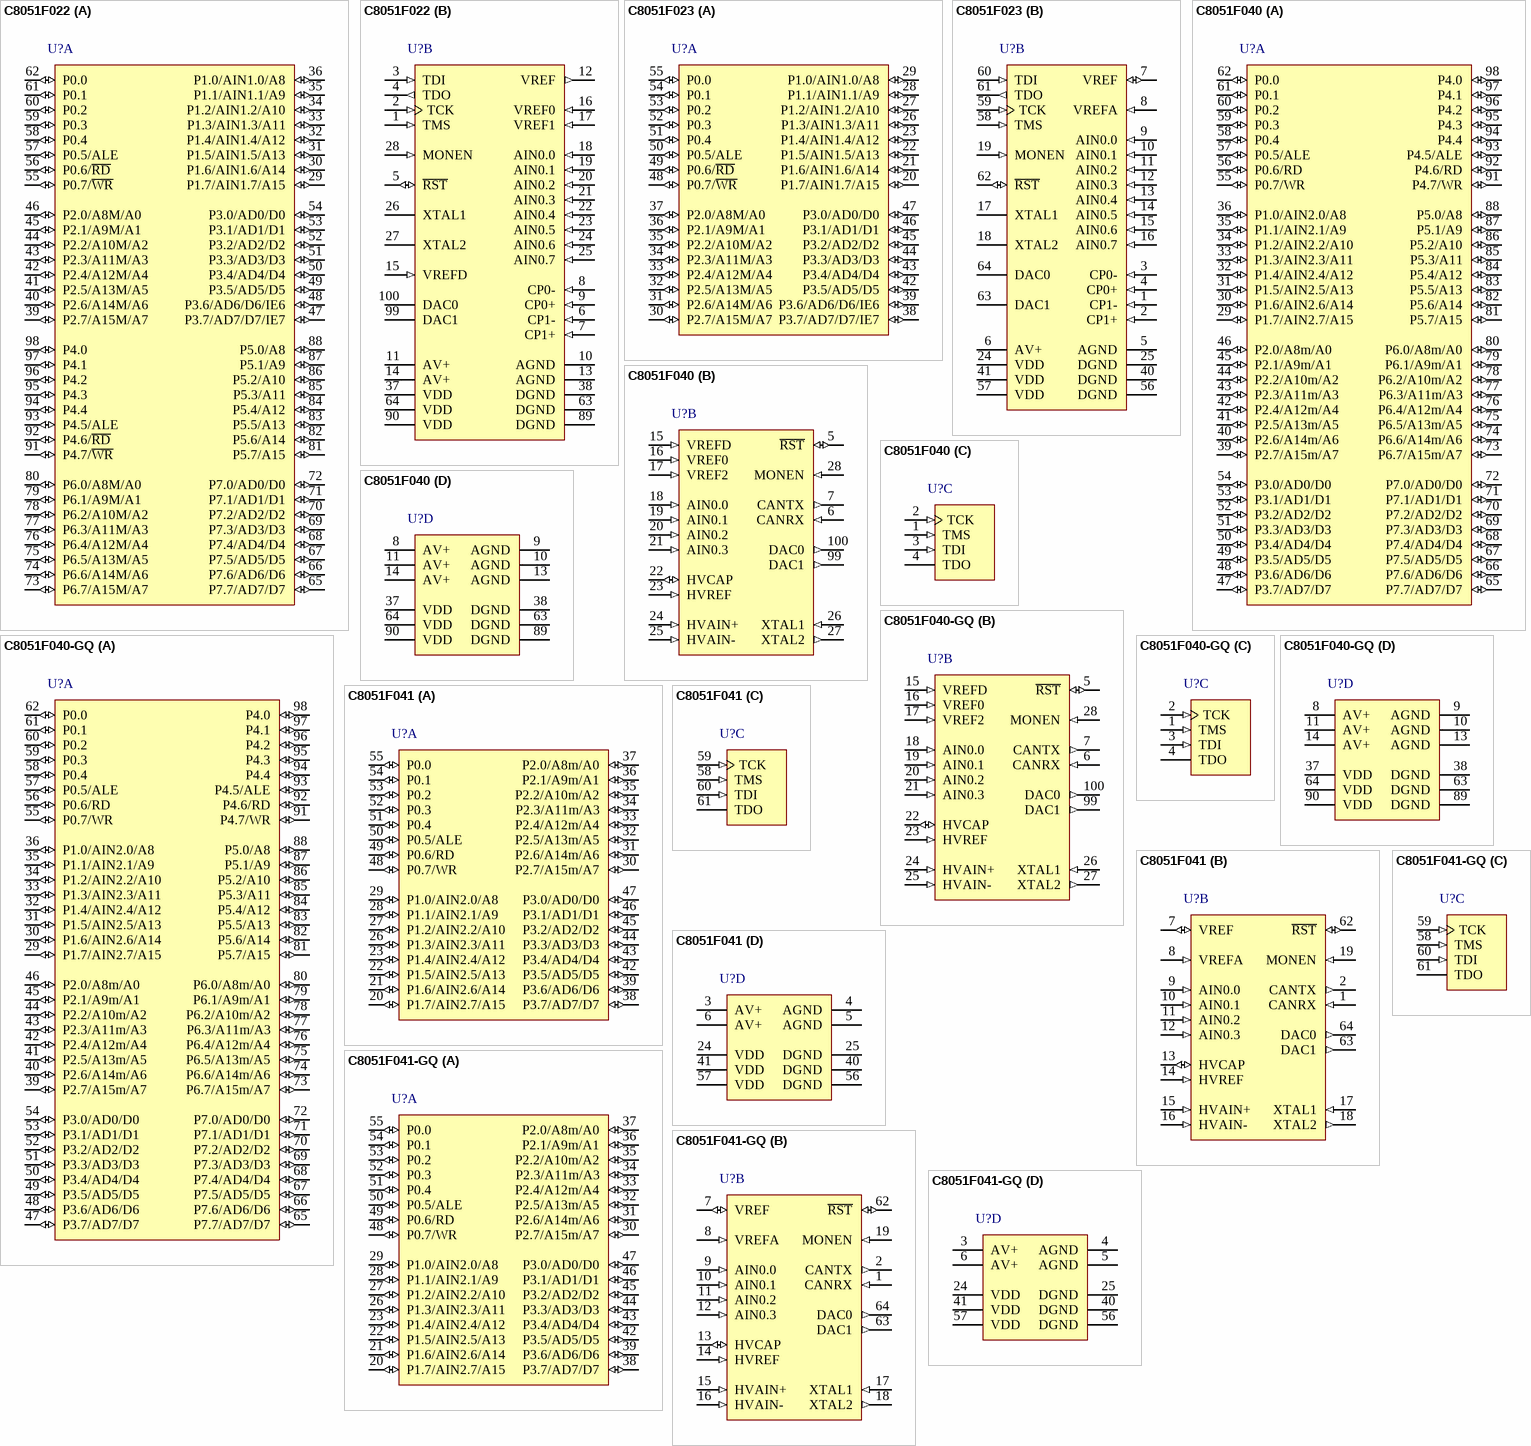
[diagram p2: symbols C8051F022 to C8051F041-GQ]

## C8051F022
designator U?
ISP Flash MCU Family, 25 MHz, 4.25 kB RAM, 64 kB Flash, -40 to 85 degC, 100-pin QFP; Manufacturer: Silicon Labs; PartNumber: C8051F022; ADC 1: 10-bit, 8-ch., 100 ksps; ADC 2: 8-bit, 8-ch., 500 ksps; AEC-Q100: FALSE; Comparators: 2; DAC: 12-bit, 2-ch.; Debug Interface: JTAG; Dig I/O Pins: 64; Flash: 64 kB; Internal Osc. Accuracy: +/-20%; MCU Core: 8051; MHz: 25; PCA Channels: 5; RAM: 4.25 kB; Temp Sensor: TRUE; Sub-Family: Analog Intensive MCUs
footprint SLAB-TQFP-100_N (QFP, 100-Leads, Body 14x14mm, Pitch 0.5mm, IPC Medium Density)
footprint SLAB-TQFP-100_L (QFP, 100-Leads, Body 14x14mm, Pitch 0.5mm, IPC High Density)
footprint SLAB-TQFP-100_M (QFP, 100-Leads, Body 14x14mm, Pitch 0.5mm, IPC Low Density)
part A pins: 29 P1.7/AIN1.7/A15 (io), 30 P1.6/AIN1.6/A14 (io), 31 P1.5/AIN1.5/A13 (io), 32 P1.4/AIN1.4/A12 (io), 33 P1.3/AIN1.3/A11 (io), 34 P1.2/AIN1.2/A10 (io), 35 P1.1/AIN1.1/A9 (io), 36 P1.0/AIN1.0/A8 (io), 39 P2.7/A15M/A7 (io), 40 P2.6/A14M/A6 (io), 41 P2.5/A13M/A5 (io), 42 P2.4/A12M/A4 (io), 43 P2.3/A11M/A3 (io), 44 P2.2/A10M/A2 (io), 45 P2.1/A9M/A1 (io), 46 P2.0/A8M/A0 (io), 47 P3.7/AD7/D7/IE7 (io), 48 P3.6/AD6/D6/IE6 (io), 49 P3.5/AD5/D5 (io), 50 P3.4/AD4/D4 (io), 51 P3.3/AD3/D3 (io), 52 P3.2/AD2/D2 (io), 53 P3.1/AD1/D1 (io), 54 P3.0/AD0/D0 (io), 55 P0.7/~{WR} (io), 56 P0.6/~{RD} (io), 57 P0.5/ALE (io), 58 P0.4 (io) "Port 0.4. See Port Input/Output section for complete description.", 59 P0.3 (io) "Port 0.3. See Port Input/Output section for complete description.", 60 P0.2 (io) "Port 0.2. See Port Input/Output section for complete description.", 61 P0.1 (io) "Port 0.1. See Port Input/Output section for complete description.", 62 P0.0 (io) "Port 0.0. See Port Input/Output section for complete description.", 65 P7.7/AD7/D7 (io), 66 P7.6/AD6/D6 (io), 67 P7.5/AD5/D5 (io), 68 P7.4/AD4/D4 (io), 69 P7.3/AD3/D3 (io), 70 P7.2/AD2/D2 (io), 71 P7.1/AD1/D1 (io), 72 P7.0/AD0/D0 (io), 73 P6.7/A15M/A7 (io), 74 P6.6/A14M/A6 (io), 75 P6.5/A13M/A5 (io), 76 P6.4/A12M/A4 (io), 77 P6.3/A11M/A3 (io), 78 P6.2/A10M/A2 (io), 79 P6.1/A9M/A1 (io), 80 P6.0/A8M/A0 (io), 81 P5.7/A15 (io), 82 P5.6/A14 (io), 83 P5.5/A13 (io), 84 P5.4/A12 (io), 85 P5.3/A11 (io), 86 P5.2/A10 (io), 87 P5.1/A9 (io), 88 P5.0/A8 (io), 91 P4.7/~{WR} (io), 92 P4.6/~{RD} (io), 93 P4.5/ALE (io), 94 P4.4 (io) "Port 4.4. See Port Input/Output section for complete description.", 95 P4.3 (io) "Port 4.3. See Port Input/Output section for complete description.", 96 P4.2 (io) "Port 4.2. See Port Input/Output section for complete description.", 97 P4.1 (io) "Port 4.1. See Port Input/Output section for complete description.", 98 P4.0 (io) "Port 4.0. See Port Input/Output section for complete description."
part B pins: 1 TMS (in) "JTAG Test Mode Select with internal pull-up.", 2 TCK (in) "JTAG Test Clock with internal pull-up.", 3 TDI (in) "JTAG Test Data Input with internal pull-up. TDI is latched on the rising edge of TCK.", 4 TDO (out) "JTAG Test Data Output with internal pull-up. Data is shifted out on TDO on the falling edge of TCK. TDO output is a tri-state driver.", 5 ~{RST} (io) "Device Reset. Open-drain output of internal VDD monitor. Is driven low when VDD is <2.7 V and MONEN is high. An external source can initiate a system reset by driving this pin low.", 6 CP1- (in) "Comparator 1 Inverting Input.", 7 CP1+ (in) "Comparator 1 Non-Inverting Input.", 8 CP0- (in) "Comparator 0 Inverting Input.", 9 CP0+ (in) "Comparator 0 Non-Inverting Input.", 10 AGND (power) "Analog Ground. Must be tied to Ground.", 11 AV+ (power) "Analog Supply Voltage. Must be tied to +2.7 to +3.6 V.", 12 VREF (out) "Bandgap Voltage Reference Output (all devices). DAC Voltage Reference Input (F021/3 only).", 13 AGND (power) "Analog Ground. Must be tied to Ground.", 14 AV+ (power) "Analog Supply Voltage. Must be tied to +2.7 to +3.6 V.", 15 VREFD (in) "DAC Voltage Reference Input.", 16 VREF0 (in) "ADC0 Voltage Reference Input.", 17 VREF1 (in) "ADC1 Voltage Reference Input.", 18 AIN0.0 (in) "ADC0 Input Channel 0 (See ADC0 Specification for complete description).", 19 AIN0.1 (in) "ADC0 Input Channel 1 (See ADC0 Specification for complete description).", 20 AIN0.2 (in) "ADC0 Input Channel 2 (See ADC0 Specification for complete description).", 21 AIN0.3 (in) "ADC0 Input Channel 3 (See ADC0 Specification for complete description).", 22 AIN0.4 (in) "ADC0 Input Channel 4 (See ADC0 Specification for complete description).", 23 AIN0.5 (in) "ADC0 Input Channel 5 (See ADC0 Specification for complete description).", 24 AIN0.6 (in) "ADC0 Input Channel 6 (See ADC0 Specification for complete description).", 25 AIN0.7 (in) "ADC0 Input Channel 7 (See ADC0 Specification for complete description).", 26 XTAL1 "Crystal Input. This pin is the return for the internal oscillator circuit for a crystal or ceramic resonator. For a precision internal clock, connect a crystal or ceramic resonator from XTAL1 to XTAL2. If overdriven by an (See Datasheet)", 27 XTAL2 "Crystal Output. This pin is the excitation driver for a crystal or ceramic resonator.", 28 MONEN (in) "VDD Monitor Enable. When tied high, this pin enables the internal VDD monitor, which forces a system reset when VDD is < 2.7 V. When tied low, the internal VDD monitor is disabled.", 37 VDD (power) "Digital Supply Voltage. Must be tied to +2.7 to +3.6 V.", 38 DGND (power) "Digital Ground. Must be tied to Ground.", 63 DGND (power) "Digital Ground. Must be tied to Ground.", 64 VDD (power) "Digital Supply Voltage. Must be tied to +2.7 to +3.6 V.", 89 DGND (power) "Digital Ground. Must be tied to Ground.", 90 VDD (power) "Digital Supply Voltage. Must be tied to +2.7 to +3.6 V.", 99 DAC1 (hiz) "Digital to Analog Converter 1 Voltage Output. (See DAC Specifica- tion for complete description).", 100 DAC0 (hiz) "Digital to Analog Converter 0 Voltage Output. (See DAC Specifica- tion for complete description)."

## C8051F023
designator U?
ISP Flash MCU Family, 25 MHz, 4.25 kB RAM, 64 kB Flash, -40 to 85 degC, 64-pin QFP; Manufacturer: Silicon Labs; PartNumber: C8051F023; ADC 1: 10-bit, 8-ch., 100 ksps; ADC 2: 8-bit, 8-ch., 500 ksps; AEC-Q100: FALSE; Comparators: 2; DAC: 12-bit, 2-ch.; Debug Interface: JTAG; Dig I/O Pins: 32; Flash: 64 kB; Internal Osc. Accuracy: +/-20%; MCU Core: 8051; MHz: 25; PCA Channels: 5; RAM: 4.25 kB; Temp Sensor: TRUE; Sub-Family: Analog Intensive MCUs
footprint SLAB-TQFP-64_N (QFP, 64-Leads, Body 10x10mm, Pitch 0.5mm, IPC Medium Density)
footprint SLAB-TQFP-64_L (QFP, 64-Leads, Body 10x10mm, Pitch 0.5mm, IPC High Density)
footprint SLAB-TQFP-64_M (QFP, 64-Leads, Body 10x10mm, Pitch 0.5mm, IPC Low Density)
part A pins: 20 P1.7/AIN1.7/A15 (io), 21 P1.6/AIN1.6/A14 (io), 22 P1.5/AIN1.5/A13 (io), 23 P1.4/AIN1.4/A12 (io), 26 P1.3/AIN1.3/A11 (io), 27 P1.2/AIN1.2/A10 (io), 28 P1.1/AIN1.1/A9 (io), 29 P1.0/AIN1.0/A8 (io), 30 P2.7/A15M/A7 (io), 31 P2.6/A14M/A6 (io), 32 P2.5/A13M/A5 (io), 33 P2.4/A12M/A4 (io), 34 P2.3/A11M/A3 (io), 35 P2.2/A10M/A2 (io), 36 P2.1/A9M/A1 (io), 37 P2.0/A8M/A0 (io), 38 P3.7/AD7/D7/IE7 (io), 39 P3.6/AD6/D6/IE6 (io), 42 P3.5/AD5/D5 (io), 43 P3.4/AD4/D4 (io), 44 P3.3/AD3/D3 (io), 45 P3.2/AD2/D2 (io), 46 P3.1/AD1/D1 (io), 47 P3.0/AD0/D0 (io), 48 P0.7/~{WR} (io), 49 P0.6/~{RD} (io), 50 P0.5/ALE (io), 51 P0.4 (io) "Port 0.4. See Port Input/Output section for complete description.", 52 P0.3 (io) "Port 0.3. See Port Input/Output section for complete description.", 53 P0.2 (io) "Port 0.2. See Port Input/Output section for complete description.", 54 P0.1 (io) "Port 0.1. See Port Input/Output section for complete description.", 55 P0.0 (io) "Port 0.0. See Port Input/Output section for complete description."
part B pins: 1 CP1- (in) "Comparator 1 Inverting Input.", 2 CP1+ (in) "Comparator 1 Non-Inverting Input.", 3 CP0- (in) "Comparator 0 Inverting Input.", 4 CP0+ (in) "Comparator 0 Non-Inverting Input.", 5 AGND (power) "Analog Ground. Must be tied to Ground.", 6 AV+ (power) "Analog Supply Voltage. Must be tied to +2.7 to +3.6 V.", 7 VREF (io) "Bandgap Voltage Reference Output (all devices). DAC Voltage Reference Input (F021/3 only).", 8 VREFA (in) "ADC0 and ADC1 Voltage Reference Input.", 9 AIN0.0 (in) "ADC0 Input Channel 0 (See ADC0 Specification for complete description).", 10 AIN0.1 (in) "ADC0 Input Channel 1 (See ADC0 Specification for complete description).", 11 AIN0.2 (in) "ADC0 Input Channel 2 (See ADC0 Specification for complete description).", 12 AIN0.3 (in) "ADC0 Input Channel 3 (See ADC0 Specification for complete description).", 13 AIN0.4 (in) "ADC0 Input Channel 4 (See ADC0 Specification for complete description).", 14 AIN0.5 (in) "ADC0 Input Channel 5 (See ADC0 Specification for complete description).", 15 AIN0.6 (in) "ADC0 Input Channel 6 (See ADC0 Specification for complete description).", 16 AIN0.7 (in) "ADC0 Input Channel 7 (See ADC0 Specification for complete description).", 17 XTAL1 "Crystal Input. This pin is the return for the internal oscillator circuit for a crystal or ceramic resonator. For a precision internal clock, connect a crystal or ceramic resonator from XTAL1 to XTAL2. If overdriven by an (See Datasheet)", 18 XTAL2 "Crystal Output. This pin is the excitation driver for a crystal or ceramic resonator.", 19 MONEN (in) "VDD Monitor Enable. When tied high, this pin enables the internal VDD monitor, which forces a system reset when VDD is < 2.7 V. When tied low, the internal VDD monitor is disabled.", 24 VDD (power) "Digital Supply Voltage. Must be tied to +2.7 to +3.6 V.", 25 DGND (power) "Digital Ground. Must be tied to Ground.", 40 DGND (power) "Digital Ground. Must be tied to Ground.", 41 VDD (power) "Digital Supply Voltage. Must be tied to +2.7 to +3.6 V.", 56 DGND (power) "Digital Ground. Must be tied to Ground.", 57 VDD (power) "Digital Supply Voltage. Must be tied to +2.7 to +3.6 V.", 58 TMS (in) "JTAG Test Mode Select with internal pull-up.", 59 TCK (in) "JTAG Test Clock with internal pull-up.", 60 TDI (in) "JTAG Test Data Input with internal pull-up. TDI is latched on the rising edge of TCK.", 61 TDO (out) "JTAG Test Data Output with internal pull-up. Data is shifted out on TDO on the falling edge of TCK. TDO output is a tri-state driver.", 62 ~{RST} (io) "Device Reset. Open-drain output of internal VDD monitor. Is driven low when VDD is <2.7 V and MONEN is high. An external source can initiate a system reset by driving this pin low.", 63 DAC1 (hiz) "Digital to Analog Converter 1 Voltage Output. (See DAC Specifica- tion for complete description).", 64 DAC0 (hiz) "Digital to Analog Converter 0 Voltage Output. (See DAC Specifica- tion for complete description)."

## C8051F040
designator U?
Mixed Signal 64KB ISP Flash MCU, 25 MIPS, 4352B RAM, 64 I/Os, 12-Bit & 8-Bit ADC, 12-Bit DAC, 100-Pin TQFP; Manufacturer: Silicon Labs; PartNumber: C8051F040
footprint TQFP-100_N (Thin QFP, 100-Leads, Body 14x14mm, Pitch 0.5mm, IPC Medium Density)
footprint TQFP-100_L (Thin QFP, 100-Leads, Body 14x14mm, Pitch 0.5mm, IPC High Density)
footprint TQFP-100_M (Thin QFP, 100-Leads, Body 14x14mm, Pitch 0.5mm, IPC Low Density)
part A pins: 29 P1.7/AIN2.7/A15 (io), 30 P1.6/AIN2.6/A14 (io), 31 P1.5/AIN2.5/A13 (io), 32 P1.4/AIN2.4/A12 (io), 33 P1.3/AIN2.3/A11 (io), 34 P1.2/AIN2.2/A10 (io), 35 P1.1/AIN2.1/A9 (io), 36 P1.0/AIN2.0/A8 (io), 39 P2.7/A15m/A7 (io), 40 P2.6/A14m/A6 (io), 41 P2.5/A13m/A5 (io), 42 P2.4/A12m/A4 (io), 43 P2.3/A11m/A3 (io), 44 P2.2/A10m/A2 (io), 45 P2.1/A9m/A1 (io), 46 P2.0/A8m/A0 (io), 47 P3.7/AD7/D7 (io), 48 P3.6/AD6/D6 (io), 49 P3.5/AD5/D5 (io), 50 P3.4/AD4/D4 (io), 51 P3.3/AD3/D3 (io), 52 P3.2/AD2/D2 (io), 53 P3.1/AD1/D1 (io), 54 P3.0/AD0/D0 (io), 55 P0.7/WR (io), 56 P0.6/RD (io), 57 P0.5/ALE (io), 58 P0.4 (io), 59 P0.3 (io), 60 P0.2 (io), 61 P0.1 (io), 62 P0.0 (io), 65 P7.7/AD7/D7 (io), 66 P7.6/AD6/D6 (io), 67 P7.5/AD5/D5 (io), 68 P7.4/AD4/D4 (io), 69 P7.3/AD3/D3 (io), 70 P7.2/AD2/D2 (io), 71 P7.1/AD1/D1 (io), 72 P7.0/AD0/D0 (io), 73 P6.7/A15m/A7 (io), 74 P6.6/A14m/A6 (io), 75 P6.5/A13m/A5 (io), 76 P6.4/A12m/A4 (io), 77 P6.3/A11m/A3 (io), 78 P6.2/A10m/A2 (io), 79 P6.1/A9m/A1 (io), 80 P6.0/A8m/A0 (io), 81 P5.7/A15 (io), 82 P5.6/A14 (io), 83 P5.5/A13 (io), 84 P5.4/A12 (io), 85 P5.3/A11 (io), 86 P5.2/A10 (io), 87 P5.1/A9 (io), 88 P5.0/A8 (io), 91 P4.7/WR (io), 92 P4.6/RD (io), 93 P4.5/ALE (io), 94 P4.4 (io), 95 P4.3 (io), 96 P4.2 (io), 97 P4.1 (io), 98 P4.0 (io)
part B pins: 5 ~{RST} (io), 6 CANRX (in), 7 CANTX (out), 15 VREFD (in), 16 VREF0 (in), 17 VREF2 (in), 18 AIN0.0 (in), 19 AIN0.1 (in), 20 AIN0.2 (in), 21 AIN0.3 (in), 22 HVCAP (io), 23 HVREF (in), 24 HVAIN+ (in), 25 HVAIN- (in), 26 XTAL1 (in), 27 XTAL2 (out), 28 MONEN (in), 99 DAC1 (out), 100 DAC0 (out)
part C pins: 1 TMS (in), 2 TCK (in), 3 TDI (in), 4 TDO (hiz)
part D pins: 8 AV+ (power), 9 AGND (power), 10 AGND (power), 11 AV+ (power), 13 AGND (power), 14 AV+ (power), 37 VDD (power), 38 DGND (power), 63 DGND (power), 64 VDD (power), 89 DGND (power), 90 VDD (power)

## C8051F040-GQ
designator U?
Mixed Signal 64KB ISP Flash MCU, 25 MIPS, 4352B RAM, 64 I/Os, 12-Bit & 8-Bit ADC, 12-Bit DAC, 100-Pin TQFP, Pb-Free; Manufacturer: Silicon Labs; PartNumber: C8051F040-GQ
footprint TQFP-100_N (Thin QFP, 100-Leads, Body 14x14mm, Pitch 0.5mm, IPC Medium Density)
footprint TQFP-100_L (Thin QFP, 100-Leads, Body 14x14mm, Pitch 0.5mm, IPC High Density)
footprint TQFP-100_M (Thin QFP, 100-Leads, Body 14x14mm, Pitch 0.5mm, IPC Low Density)
part A pins: 29 P1.7/AIN2.7/A15 (io), 30 P1.6/AIN2.6/A14 (io), 31 P1.5/AIN2.5/A13 (io), 32 P1.4/AIN2.4/A12 (io), 33 P1.3/AIN2.3/A11 (io), 34 P1.2/AIN2.2/A10 (io), 35 P1.1/AIN2.1/A9 (io), 36 P1.0/AIN2.0/A8 (io), 39 P2.7/A15m/A7 (io), 40 P2.6/A14m/A6 (io), 41 P2.5/A13m/A5 (io), 42 P2.4/A12m/A4 (io), 43 P2.3/A11m/A3 (io), 44 P2.2/A10m/A2 (io), 45 P2.1/A9m/A1 (io), 46 P2.0/A8m/A0 (io), 47 P3.7/AD7/D7 (io), 48 P3.6/AD6/D6 (io), 49 P3.5/AD5/D5 (io), 50 P3.4/AD4/D4 (io), 51 P3.3/AD3/D3 (io), 52 P3.2/AD2/D2 (io), 53 P3.1/AD1/D1 (io), 54 P3.0/AD0/D0 (io), 55 P0.7/WR (io), 56 P0.6/RD (io), 57 P0.5/ALE (io), 58 P0.4 (io), 59 P0.3 (io), 60 P0.2 (io), 61 P0.1 (io), 62 P0.0 (io), 65 P7.7/AD7/D7 (io), 66 P7.6/AD6/D6 (io), 67 P7.5/AD5/D5 (io), 68 P7.4/AD4/D4 (io), 69 P7.3/AD3/D3 (io), 70 P7.2/AD2/D2 (io), 71 P7.1/AD1/D1 (io), 72 P7.0/AD0/D0 (io), 73 P6.7/A15m/A7 (io), 74 P6.6/A14m/A6 (io), 75 P6.5/A13m/A5 (io), 76 P6.4/A12m/A4 (io), 77 P6.3/A11m/A3 (io), 78 P6.2/A10m/A2 (io), 79 P6.1/A9m/A1 (io), 80 P6.0/A8m/A0 (io), 81 P5.7/A15 (io), 82 P5.6/A14 (io), 83 P5.5/A13 (io), 84 P5.4/A12 (io), 85 P5.3/A11 (io), 86 P5.2/A10 (io), 87 P5.1/A9 (io), 88 P5.0/A8 (io), 91 P4.7/WR (io), 92 P4.6/RD (io), 93 P4.5/ALE (io), 94 P4.4 (io), 95 P4.3 (io), 96 P4.2 (io), 97 P4.1 (io), 98 P4.0 (io)
part B pins: 5 ~{RST} (io), 6 CANRX (in), 7 CANTX (out), 15 VREFD (in), 16 VREF0 (in), 17 VREF2 (in), 18 AIN0.0 (in), 19 AIN0.1 (in), 20 AIN0.2 (in), 21 AIN0.3 (in), 22 HVCAP (io), 23 HVREF (in), 24 HVAIN+ (in), 25 HVAIN- (in), 26 XTAL1 (in), 27 XTAL2 (out), 28 MONEN (in), 99 DAC1 (out), 100 DAC0 (out)
part C pins: 1 TMS (in), 2 TCK (in), 3 TDI (in), 4 TDO (hiz)
part D pins: 8 AV+ (power), 9 AGND (power), 10 AGND (power), 11 AV+ (power), 13 AGND (power), 14 AV+ (power), 37 VDD (power), 38 DGND (power), 63 DGND (power), 64 VDD (power), 89 DGND (power), 90 VDD (power)

## C8051F041
designator U?
Mixed Signal 64KB ISP Flash MCU, 25 MIPS, 4352B RAM, 32 I/Os, 12-Bit & 8-Bit ADC, 12-Bit DAC, 64-Pin TQFP; Manufacturer: Silicon Labs; PartNumber: C8051F041
footprint TQFP-64_N (Thin QFP, 64-Leads, Body 10x10mm, Pitch 0.5mm, IPC Medium Density)
footprint TQFP-64_L (Thin QFP, 64-Leads, Body 10x10mm, Pitch 0.5mm, IPC High Density)
footprint TQFP-64_M (Thin QFP, 64-Leads, Body 10x10mm, Pitch 0.5mm, IPC Low Density)
part A pins: 20 P1.7/AIN2.7/A15 (io), 21 P1.6/AIN2.6/A14 (io), 22 P1.5/AIN2.5/A13 (io), 23 P1.4/AIN2.4/A12 (io), 26 P1.3/AIN2.3/A11 (io), 27 P1.2/AIN2.2/A10 (io), 28 P1.1/AIN2.1/A9 (io), 29 P1.0/AIN2.0/A8 (io), 30 P2.7/A15m/A7 (io), 31 P2.6/A14m/A6 (io), 32 P2.5/A13m/A5 (io), 33 P2.4/A12m/A4 (io), 34 P2.3/A11m/A3 (io), 35 P2.2/A10m/A2 (io), 36 P2.1/A9m/A1 (io), 37 P2.0/A8m/A0 (io), 38 P3.7/AD7/D7 (io), 39 P3.6/AD6/D6 (io), 42 P3.5/AD5/D5 (io), 43 P3.4/AD4/D4 (io), 44 P3.3/AD3/D3 (io), 45 P3.2/AD2/D2 (io), 46 P3.1/AD1/D1 (io), 47 P3.0/AD0/D0 (io), 48 P0.7/WR (io), 49 P0.6/RD (io), 50 P0.5/ALE (io), 51 P0.4 (io), 52 P0.3 (io), 53 P0.2 (io), 54 P0.1 (io), 55 P0.0 (io)
part B pins: 1 CANRX (in), 2 CANTX (out), 7 VREF (io), 8 VREFA (in), 9 AIN0.0 (in), 10 AIN0.1 (in), 11 AIN0.2 (in), 12 AIN0.3 (in), 13 HVCAP (io), 14 HVREF (in), 15 HVAIN+ (in), 16 HVAIN- (in), 17 XTAL1 (in), 18 XTAL2 (out), 19 MONEN (in), 62 ~{RST} (io), 63 DAC1 (out), 64 DAC0 (out)
part C pins: 58 TMS (in), 59 TCK (in), 60 TDI (in), 61 TDO (hiz)
part D pins: 3 AV+ (power), 4 AGND (power), 5 AGND (power), 6 AV+ (power), 24 VDD (power), 25 DGND (power), 40 DGND (power), 41 VDD (power), 56 DGND (power), 57 VDD (power)

## C8051F041-GQ
designator U?
Mixed Signal 64KB ISP Flash MCU, 25 MIPS, 4352B RAM, 32 I/Os, 12-Bit & 8-Bit ADC, 12-Bit DAC, 64-Pin TQFP, Pb-Free; Manufacturer: Silicon Labs; PartNumber: C8051F041-GQ
footprint TQFP-64_N (Thin QFP, 64-Leads, Body 10x10mm, Pitch 0.5mm, IPC Medium Density)
footprint TQFP-64_L (Thin QFP, 64-Leads, Body 10x10mm, Pitch 0.5mm, IPC High Density)
footprint TQFP-64_M (Thin QFP, 64-Leads, Body 10x10mm, Pitch 0.5mm, IPC Low Density)
part A pins: 20 P1.7/AIN2.7/A15 (io), 21 P1.6/AIN2.6/A14 (io), 22 P1.5/AIN2.5/A13 (io), 23 P1.4/AIN2.4/A12 (io), 26 P1.3/AIN2.3/A11 (io), 27 P1.2/AIN2.2/A10 (io), 28 P1.1/AIN2.1/A9 (io), 29 P1.0/AIN2.0/A8 (io), 30 P2.7/A15m/A7 (io), 31 P2.6/A14m/A6 (io), 32 P2.5/A13m/A5 (io), 33 P2.4/A12m/A4 (io), 34 P2.3/A11m/A3 (io), 35 P2.2/A10m/A2 (io), 36 P2.1/A9m/A1 (io), 37 P2.0/A8m/A0 (io), 38 P3.7/AD7/D7 (io), 39 P3.6/AD6/D6 (io), 42 P3.5/AD5/D5 (io), 43 P3.4/AD4/D4 (io), 44 P3.3/AD3/D3 (io), 45 P3.2/AD2/D2 (io), 46 P3.1/AD1/D1 (io), 47 P3.0/AD0/D0 (io), 48 P0.7/WR (io), 49 P0.6/RD (io), 50 P0.5/ALE (io), 51 P0.4 (io), 52 P0.3 (io), 53 P0.2 (io), 54 P0.1 (io), 55 P0.0 (io)
part B pins: 1 CANRX (in), 2 CANTX (out), 7 VREF (io), 8 VREFA (in), 9 AIN0.0 (in), 10 AIN0.1 (in), 11 AIN0.2 (in), 12 AIN0.3 (in), 13 HVCAP (io), 14 HVREF (in), 15 HVAIN+ (in), 16 HVAIN- (in), 17 XTAL1 (in), 18 XTAL2 (out), 19 MONEN (in), 62 ~{RST} (io), 63 DAC1 (out), 64 DAC0 (out)
part C pins: 58 TMS (in), 59 TCK (in), 60 TDI (in), 61 TDO (hiz)
part D pins: 3 AV+ (power), 4 AGND (power), 5 AGND (power), 6 AV+ (power), 24 VDD (power), 25 DGND (power), 40 DGND (power), 41 VDD (power), 56 DGND (power), 57 VDD (power)

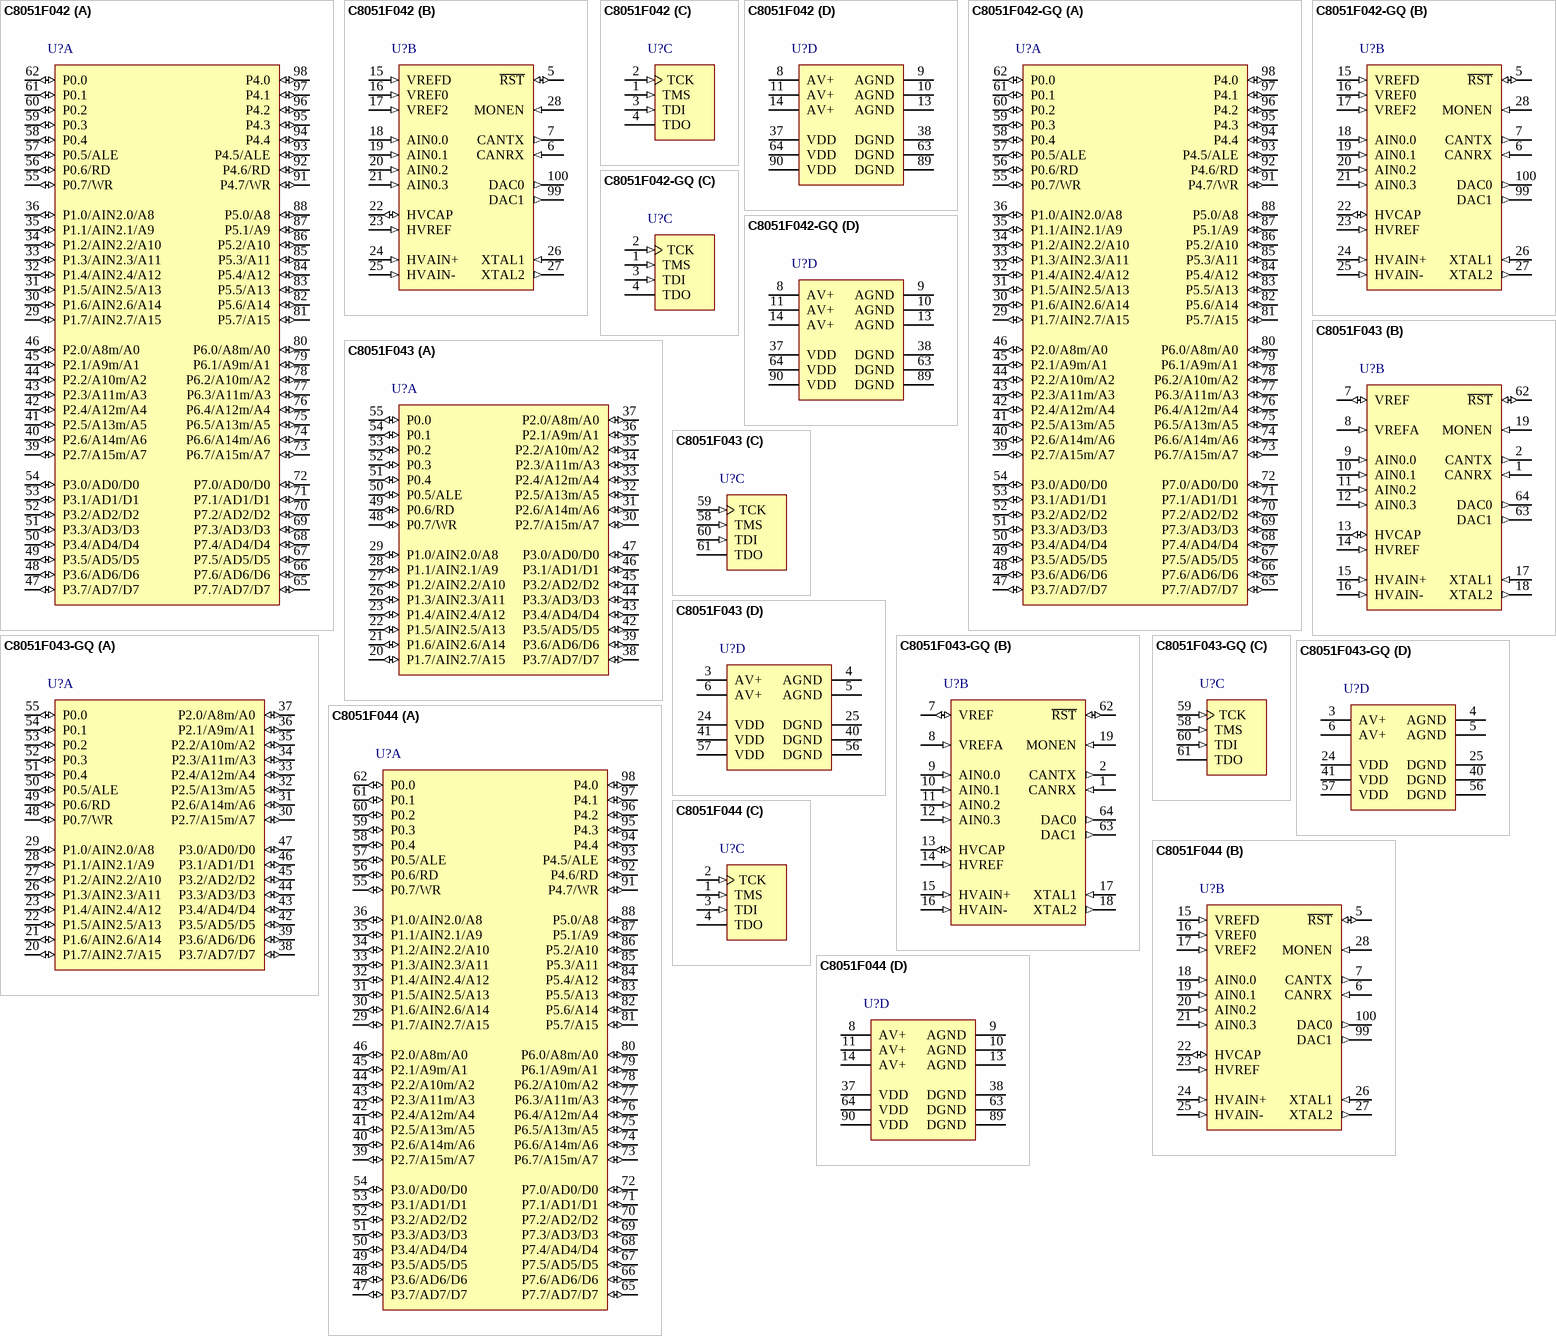
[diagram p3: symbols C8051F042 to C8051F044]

## C8051F042
designator U?
Mixed Signal 64KB ISP Flash MCU, 25 MIPS, 4352B RAM, 64 I/Os, 10-Bit & 8-Bit ADC, 12-Bit DAC, 100-Pin TQFP; Manufacturer: Silicon Labs; PartNumber: C8051F042
footprint TQFP-100_N (Thin QFP, 100-Leads, Body 14x14mm, Pitch 0.5mm, IPC Medium Density)
footprint TQFP-100_L (Thin QFP, 100-Leads, Body 14x14mm, Pitch 0.5mm, IPC High Density)
footprint TQFP-100_M (Thin QFP, 100-Leads, Body 14x14mm, Pitch 0.5mm, IPC Low Density)
part A pins: 29 P1.7/AIN2.7/A15 (io), 30 P1.6/AIN2.6/A14 (io), 31 P1.5/AIN2.5/A13 (io), 32 P1.4/AIN2.4/A12 (io), 33 P1.3/AIN2.3/A11 (io), 34 P1.2/AIN2.2/A10 (io), 35 P1.1/AIN2.1/A9 (io), 36 P1.0/AIN2.0/A8 (io), 39 P2.7/A15m/A7 (io), 40 P2.6/A14m/A6 (io), 41 P2.5/A13m/A5 (io), 42 P2.4/A12m/A4 (io), 43 P2.3/A11m/A3 (io), 44 P2.2/A10m/A2 (io), 45 P2.1/A9m/A1 (io), 46 P2.0/A8m/A0 (io), 47 P3.7/AD7/D7 (io), 48 P3.6/AD6/D6 (io), 49 P3.5/AD5/D5 (io), 50 P3.4/AD4/D4 (io), 51 P3.3/AD3/D3 (io), 52 P3.2/AD2/D2 (io), 53 P3.1/AD1/D1 (io), 54 P3.0/AD0/D0 (io), 55 P0.7/WR (io), 56 P0.6/RD (io), 57 P0.5/ALE (io), 58 P0.4 (io), 59 P0.3 (io), 60 P0.2 (io), 61 P0.1 (io), 62 P0.0 (io), 65 P7.7/AD7/D7 (io), 66 P7.6/AD6/D6 (io), 67 P7.5/AD5/D5 (io), 68 P7.4/AD4/D4 (io), 69 P7.3/AD3/D3 (io), 70 P7.2/AD2/D2 (io), 71 P7.1/AD1/D1 (io), 72 P7.0/AD0/D0 (io), 73 P6.7/A15m/A7 (io), 74 P6.6/A14m/A6 (io), 75 P6.5/A13m/A5 (io), 76 P6.4/A12m/A4 (io), 77 P6.3/A11m/A3 (io), 78 P6.2/A10m/A2 (io), 79 P6.1/A9m/A1 (io), 80 P6.0/A8m/A0 (io), 81 P5.7/A15 (io), 82 P5.6/A14 (io), 83 P5.5/A13 (io), 84 P5.4/A12 (io), 85 P5.3/A11 (io), 86 P5.2/A10 (io), 87 P5.1/A9 (io), 88 P5.0/A8 (io), 91 P4.7/WR (io), 92 P4.6/RD (io), 93 P4.5/ALE (io), 94 P4.4 (io), 95 P4.3 (io), 96 P4.2 (io), 97 P4.1 (io), 98 P4.0 (io)
part B pins: 5 ~{RST} (io), 6 CANRX (in), 7 CANTX (out), 15 VREFD (in), 16 VREF0 (in), 17 VREF2 (in), 18 AIN0.0 (in), 19 AIN0.1 (in), 20 AIN0.2 (in), 21 AIN0.3 (in), 22 HVCAP (io), 23 HVREF (in), 24 HVAIN+ (in), 25 HVAIN- (in), 26 XTAL1 (in), 27 XTAL2 (out), 28 MONEN (in), 99 DAC1 (out), 100 DAC0 (out)
part C pins: 1 TMS (in), 2 TCK (in), 3 TDI (in), 4 TDO (hiz)
part D pins: 8 AV+ (power), 9 AGND (power), 10 AGND (power), 11 AV+ (power), 13 AGND (power), 14 AV+ (power), 37 VDD (power), 38 DGND (power), 63 DGND (power), 64 VDD (power), 89 DGND (power), 90 VDD (power)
